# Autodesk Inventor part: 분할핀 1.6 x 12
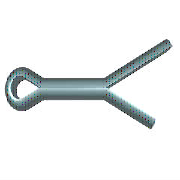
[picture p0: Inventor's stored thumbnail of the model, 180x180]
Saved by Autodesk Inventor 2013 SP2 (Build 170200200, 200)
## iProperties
IsCustomPart: 1
Created: 2012-02
Part Number: 분할핀 1.6 x 12
Material: 강철, 연강
Description: 분할 핀
Document SubType Name: Modeling
Standard: KS B 1321
Designer: mduedu
Standards Organization: KS
Language: ko-KR
Size Designation: 1.6 x  12
Categories: <MemberInstance><Categories><Category DisplayName="조임쇠" InternalName="e4da775c-781d-43d5-af7c-5136215cf5a6" Mnemonic="FSTN"><Category DisplayName="핀" InternalNa
Density: 1 g/cm^3
Author: mduedu
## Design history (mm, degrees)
sketch "스케치1"
  geometry: L1 (0, 0.7)-(7, 0.7); L2 (0, -0.7)-(7, -0.7); L3 (7, 0.7)-(12, 2.616); L4 (12, 2.616)-(12.234, 2.005); L5 (12.234, 2.005)-(7, 0); L6 (7, 0)-(14.734, -2.963); L7 (14.734, -2.963)-(14.5, -3.573); L8 (14.5, -3.573)-(7, -0.7); L9 (0, 0)-(-1.528, -0.645); L10 (0, 0)-(-1.528, 0.645); L11 (0, 0.7)-(0, -0.7); L12 (0, 0.7)-(-1.204, 1.267); L13 (0, -0.7)-(-1.204, -1.267); L14 (-3.2, 0)-(7, 0); L15 (7, 0.7)-(7, -0.7); A1 r 1.4 centre (-1.8, 0) between (-1.204, 1.267) and (-1.204, -1.267); A2 r 0.7 centre (-1.8, 0) between (-1.528, 0.645) and (-1.528, -0.645); 1 further point
  constraints: 30 end point, 5 point on circle, 4 parallel, 4 perpendicular, 4 point on line, 4 tangent, 2 centre point, 2 midpoint, 1 coincident, 1 horizontal
  dimensions: "d0" = 7 distance of L1.start L1.end (= MSIAB); "d1" = 12 horizontal distance of L1.start L3.end (= SNLG); "d2" = 159.037 deg angle of L1 L3; "d3" = 159.037 deg angle of L2 L8; "d4" = 2.5 horizontal distance of L3.end L7.end (= LGDIF); "d5" = 0.7 radius of A2 (= -0.5 x SNND1 + 0.5 x KBR); "d6" = 1.4 radius of A1 (= 0.5 x KBR); "d7" = 0.7 distance from line of L1 L9.start (= 0.5 x SNND1); "d8" = 0.7 distance between parallel lines of L2 L14 (= 0.5 x SNND1); "d9" = 1.8 distance from line of L11 A1.centre (= KOL - 0.5 x KBR)
extrude "본체" new body sketch "스케치1" stored distance "d10" = 1.4 (= SNND1); taper "d11" = 0 deg
workaxis "Work Axis1"
workplane "Work Plane1"
workplane "Work Plane3"
body "Solid1"
fillet "모깎기" dims "d12" = 0.49 (= 0.35 x SNND1)
other parameters: "SNND" = 1.6 [user parameter], "SNLG" = 12 [user parameter; used in 1 equation term], "SNND1" = 1.4 [user parameter; used in 5 equation terms], "KBR" = 2.8 [user parameter; used in 3 equation terms], "KOL" = 3.2 [user parameter; used in 1 equation term], "LGDIF" = 2.5 [user parameter; used in 1 equation term], "MSIAB" = 7 [user parameter; used in 1 equation term], "d15" = 0, "d16" = 0, "d17" = 0, "NNDMAX" = 7 [user parameter], "DSH" = 6 [user parameter], "NNDMIN" = 5.5 [user parameter]
